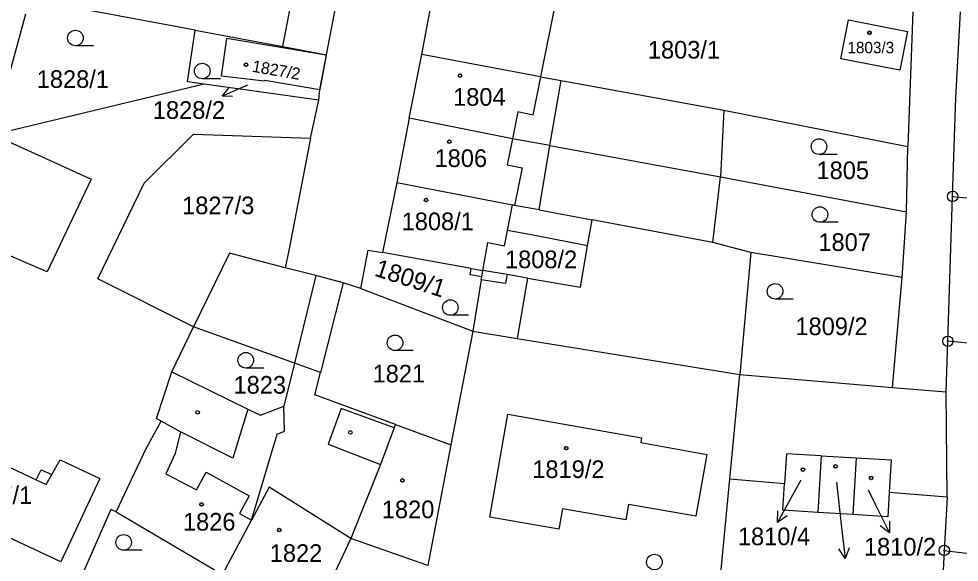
# Model space of a CAD drawing. Extents: x -593183 to -588034, y -1130415 to -1124994.
# Drawn here: x -590407.9 to -590317.4, y -1129215.7 to -1129163.3 of the extents above; entities that cross this region are included whole.
import ezdxf

# ---------------------------------------------------------------- set-up
doc = ezdxf.new("R2010")
doc.units = 0
for name, color, linetype in [('Vrstva 1', 7, 'Continuous'), ('Vrstva 16', 7, 'Continuous'), ('Vrstva 18', 7, 'Continuous'), ('Vrstva 19', 7, 'Continuous'), ('Vrstva 24', 7, 'Continuous'), ('Vrstva 25', 7, 'Continuous'), ('Vrstva 4', 7, 'Continuous')]:
    doc.layers.add(name, color=color, linetype=linetype)

msp = doc.modelspace()

# ---------------------------------------------------------------- linework, layer by layer
at = {"layer": 'Vrstva 1'}
for p, q in [((-590369.15, -1129166.78), (-590367.73, -1129159.34)), ((-590390.98, -1129164.42), (-590406.84, -1129161.45)), ((-590378.33, -1129166.8), (-590377.25, -1129161.25)), ((-590382.52, -1129166), (-590381.79, -1129162.16)), ((-590356.22, -1129161.56), (-590357.7, -1129168.92)), ((-590407.29, -1129162.87), (-590410.48, -1129174.52)), ((-590321.86, -1129162.66), (-590322.32, -1129175.65)), ((-590317.71, -1129170.96), (-590317.25, -1129162.67)), ((-590328.78, -1129167.18), (-590328.05, -1129163.42)), ((-590328.05, -1129163.42), (-590322.37, -1129164.54)), ((-590391.69, -1129169.4), (-590390.98, -1129164.42)), ((-590390.98, -1129164.42), (-590388.21, -1129164.94)), ((-590388.21, -1129164.94), (-590383.54, -1129165.82)), ((-590322.37, -1129164.54), (-590323.1, -1129168.29)), ((-590388.42, -1129168.86), (-590387.92, -1129165.22)), ((-590378.35, -1129166.84), (-590387.92, -1129165.22)), ((-590383.54, -1129165.82), (-590382.52, -1129166)), ((-590382.52, -1129166), (-590378.33, -1129166.8)), ((-590378.96, -1129170.14), (-590378.33, -1129166.8)), ((-590378.35, -1129166.84), (-590378.96, -1129170.14)), ((-590370.37, -1129172.89), (-590369.15, -1129166.78)), ((-590323.1, -1129168.29), (-590328.78, -1129167.18)), ((-590390.09, -1129169.62), (-590391.69, -1129169.4)), ((-590384.3, -1129169.35), (-590388.42, -1129168.86)), ((-590384.26, -1129169.23), (-590384.3, -1129169.35)), ((-590384.26, -1129169.23), (-590378.96, -1129170.14)), ((-590357.7, -1129168.92), (-590355.73, -1129169.28)), ((-590356.8, -1129175.55), (-590355.73, -1129169.28)), ((-590355.73, -1129169.28), (-590340.05, -1129172.13)), ((-590390.09, -1129169.62), (-590410.48, -1129174.52)), ((-590379.04, -1129171.16), (-590390.09, -1129169.62)), ((-590379.04, -1129171.16), (-590378.96, -1129170.14)), ((-590379.85, -1129174.84), (-590379.04, -1129171.16)), ((-590318.02, -1129180.44), (-590317.71, -1129170.96)), ((-590340.05, -1129172.13), (-590322.32, -1129175.65)), ((-590370.37, -1129172.89), (-590371.55, -1129179.1)), ((-590360.41, -1129174.88), (-590370.37, -1129172.89)), ((-590395.88, -1129179.17), (-590391.11, -1129174.46)), ((-590391.11, -1129174.46), (-590379.85, -1129174.84)), ((-590379.85, -1129174.84), (-590381.96, -1129185.64)), ((-590356.8, -1129175.55), (-590360.41, -1129174.88)), ((-590357.85, -1129181.75), (-590356.8, -1129175.55)), ((-590356.8, -1129175.55), (-590340.36, -1129178.57)), ((-590322.47, -1129181.93), (-590322.32, -1129175.65)), ((-590340.36, -1129178.57), (-590322.47, -1129181.93)), ((-590400.33, -1129188.4), (-590395.88, -1129179.17)), ((-590371.55, -1129179.1), (-590372.91, -1129185.84)), ((-590371.55, -1129179.1), (-590360.41, -1129181.27)), ((-590318.48, -1129194.4), (-590318.02, -1129180.44)), ((-590318.02, -1129180.44), (-590301.13, -1129182.05)), ((-590360.89, -1129183.72), (-590360.41, -1129181.27)), ((-590360.21, -1129181.31), (-590360.41, -1129181.27)), ((-590357.85, -1129181.75), (-590360.21, -1129181.31)), ((-590357.85, -1129181.75), (-590352.74, -1129182.71)), ((-590322.88, -1129188.25), (-590322.47, -1129181.93)), ((-590353.17, -1129185.2), (-590352.74, -1129182.71)), ((-590341.12, -1129184.9), (-590352.74, -1129182.71)), ((-590361.17, -1129185.19), (-590360.89, -1129183.72)), ((-590363.26, -1129187.58), (-590362.78, -1129184.9)), ((-590362.78, -1129184.9), (-590361.17, -1129185.19)), ((-590337.45, -1129185.84), (-590341.12, -1129184.9)), ((-590387.66, -1129185.9), (-590391.14, -1129193.02)), ((-590382.29, -1129187.32), (-590387.66, -1129185.9)), ((-590381.96, -1129185.64), (-590382.29, -1129187.32)), ((-590375.01, -1129189.31), (-590374.3, -1129185.62)), ((-590374.3, -1129185.62), (-590372.91, -1129185.84)), ((-590364.38, -1129187.38), (-590372.91, -1129185.84)), ((-590353.85, -1129189.19), (-590353.17, -1129185.2)), ((-590322.88, -1129188.25), (-590337.45, -1129185.84)), ((-590379.34, -1129188.07), (-590382.29, -1129187.32)), ((-590364.49, -1129188), (-590364.38, -1129187.38)), ((-590363.37, -1129188.2), (-590363.26, -1129187.58)), ((-590391.14, -1129193.02), (-590400.33, -1129188.4)), ((-590376.71, -1129188.78), (-590379.34, -1129188.07)), ((-590363.37, -1129188.2), (-590364.49, -1129188)), ((-590363.42, -1129188.47), (-590363.37, -1129188.2)), ((-590361.07, -1129188.84), (-590363.42, -1129188.47)), ((-590360.93, -1129187.98), (-590361.07, -1129188.84)), ((-590358.97, -1129188.31), (-590360.93, -1129187.98)), ((-590358.97, -1129188.31), (-590359.96, -1129194.13)), ((-590358.97, -1129188.31), (-590353.85, -1129189.19)), ((-590323.8, -1129198.84), (-590322.88, -1129188.25)), ((-590375.01, -1129189.31), (-590376.71, -1129188.78)), ((-590375.01, -1129189.31), (-590364.22, -1129193.44)), ((-590393.22, -1129197.36), (-590391.14, -1129193.02)), ((-590381.41, -1129196.5), (-590391.14, -1129193.02)), ((-590364.22, -1129193.44), (-590366.33, -1129204.39)), ((-590364.22, -1129193.44), (-590359.96, -1129194.13)), ((-590359.96, -1129194.13), (-590338.51, -1129197.6)), ((-590318.64, -1129199.27), (-590318.48, -1129194.4)), ((-590302.44, -1129195.96), (-590318.48, -1129194.4)), ((-590381.41, -1129196.5), (-590382.44, -1129200.67)), ((-590378.9, -1129197.42), (-590381.41, -1129196.5)), ((-590394.68, -1129201.84), (-590393.22, -1129197.36)), ((-590393.22, -1129197.36), (-590385.9, -1129200.93)), ((-590379.43, -1129199.55), (-590378.9, -1129197.42)), ((-590339.47, -1129207.66), (-590338.51, -1129197.6)), ((-590338.51, -1129197.6), (-590323.8, -1129198.84)), ((-590318.55, -1129209.43), (-590318.64, -1129199.27)), ((-590371.67, -1129202.42), (-590379.43, -1129199.55)), ((-590385.9, -1129200.93), (-590384.66, -1129201.52)), ((-590384.66, -1129201.52), (-590382.44, -1129200.67)), ((-590382.36, -1129203.07), (-590382.44, -1129200.67)), ((-590395.66, -1129204.68), (-590394.24, -1129202.11)), ((-590394.24, -1129202.11), (-590394.68, -1129201.84)), ((-590362.6, -1129211.36), (-590360.86, -1129201.43)), ((-590360.86, -1129201.43), (-590347.98, -1129203.69)), ((-590383.06, -1129203.35), (-590382.36, -1129203.07)), ((-590371.79, -1129202.73), (-590373.11, -1129206.26)), ((-590371.67, -1129202.42), (-590371.79, -1129202.73)), ((-590371.67, -1129202.42), (-590366.33, -1129204.39)), ((-590385.53, -1129211.63), (-590383.06, -1129203.35)), ((-590347.98, -1129203.69), (-590348.06, -1129204.16)), ((-590398.57, -1129210.83), (-590395.66, -1129204.68)), ((-590366.33, -1129204.39), (-590368.57, -1129216)), ((-590348.06, -1129204.16), (-590341.68, -1129205.32)), ((-590341.68, -1129205.32), (-590342.76, -1129211.26)), ((-590334.02, -1129205.24), (-590334.2, -1129208.11)), ((-590330.68, -1129205.43), (-590334.02, -1129205.24)), ((-590330.68, -1129205.43), (-590331, -1129210.89)), ((-590330.68, -1129205.43), (-590327.31, -1129205.63)), ((-590327.31, -1129205.63), (-590327.63, -1129211.08)), ((-590327.31, -1129205.63), (-590323.94, -1129205.83)), ((-590323.94, -1129205.83), (-590324.12, -1129208.96)), ((-590373.11, -1129206.26), (-590375.96, -1129213.4)), ((-590341.15, -1129225.34), (-590339.47, -1129207.66)), ((-590339.47, -1129207.66), (-590334.2, -1129208.11)), ((-590334.37, -1129210.69), (-590334.2, -1129208.11)), ((-590324.12, -1129208.96), (-590324.26, -1129211.31)), ((-590318.55, -1129209.43), (-590324.12, -1129208.96)), ((-590318.55, -1129209.43), (-590318.83, -1129214.55)), ((-590349.23, -1129210.13), (-590349.49, -1129211.61)), ((-590342.76, -1129211.26), (-590349.23, -1129210.13)), ((-590399.1, -1129210.62), (-590403.83, -1129221.39)), ((-590398.57, -1129210.83), (-590399.1, -1129210.62)), ((-590398.57, -1129210.83), (-590388.33, -1129216.89)), ((-590355.6, -1129210.55), (-590355.94, -1129212.52)), ((-590349.49, -1129211.61), (-590355.6, -1129210.55)), ((-590331, -1129210.89), (-590334.37, -1129210.69)), ((-590327.63, -1129211.08), (-590331, -1129210.89)), ((-590324.26, -1129211.31), (-590327.63, -1129211.08)), ((-590388.33, -1129216.89), (-590385.53, -1129211.63)), ((-590355.94, -1129212.52), (-590362.6, -1129211.36)), ((-590375.96, -1129213.4), (-590378.66, -1129219.07)), ((-590318.83, -1129214.55), (-590319.63, -1129229.39)), ((-590318.83, -1129214.55), (-590304.37, -1129216.34))]:
    msp.add_line(p, q, dxfattribs=at)
at = {"layer": 'Vrstva 16'}
for p, q in [((-590332.64, -1129207.77), (-590333.44, -1129209.22)), ((-590329.19, -1129207.99), (-590328.71, -1129212.36)), ((-590326.17, -1129208.72), (-590325.44, -1129210.17))]:
    msp.add_line(p, q, dxfattribs=at)
at = {"layer": 'Vrstva 24'}
for centre, radius in [((-590318.02, -1129180.44), 0.5), ((-590318.02, -1129180.44), 0.0327), ((-590318.48, -1129194.4), 0.5), ((-590318.48, -1129194.4), 0.0327), ((-590318.83, -1129214.55), 0.5), ((-590318.83, -1129214.55), 0.0327)]:
    msp.add_circle(centre, radius, dxfattribs=at)
at = {"layer": 'Vrstva 25'}
for p, q in [((-590400.75, -1129165.93), (-590402.5, -1129165.93)), ((-590388.53, -1129169.11), (-590390.28, -1129169.11)), ((-590385.93, -1129169.74), (-590388.36, -1129170.773)), ((-590329.14, -1129176.39), (-590330.89, -1129176.39)), ((-590329.05, -1129182.94), (-590330.8, -1129182.94)), ((-590333.37, -1129190.34), (-590335.12, -1129190.34)), ((-590364.64, -1129191.9), (-590366.39, -1129191.9)), ((-590369.96, -1129195.3), (-590371.71, -1129195.3)), ((-590384.34, -1129196.98), (-590386.09, -1129196.98)), ((-590333.44, -1129209.22), (-590334.887, -1129211.848)), ((-590325.44, -1129210.17), (-590324.094, -1129212.851)), ((-590328.71, -1129212.36), (-590328.384, -1129215.342)), ((-590396.1, -1129214.53), (-590397.85, -1129214.53))]:
    msp.add_line(p, q, dxfattribs=at)
for points in [[(-590387.378, -1129170.833), (-590388.36, -1129170.773), (-590387.722, -1129170.023)], [(-590333.967, -1129211.213), (-590334.887, -1129211.848), (-590334.843, -1129210.731)], [(-590324.096, -1129211.733), (-590324.094, -1129212.851), (-590324.99, -1129212.182)], [(-590327.996, -1129214.294), (-590328.384, -1129215.342), (-590328.99, -1129214.402)]]:
    msp.add_lwpolyline(points, dxfattribs=at)
for centre, radius in [((-590402.5, -1129165.18), 0.75), ((-590326.03, -1129164.68), 0.175), ((-590326.03, -1129164.68), 0.15), ((-590390.28, -1129168.36), 0.75), ((-590386.07, -1129167.75), 0.175), ((-590386.07, -1129167.75), 0.15), ((-590365.46, -1129168.8), 0.175), ((-590365.46, -1129168.8), 0.15), ((-590366.49, -1129175.17), 0.175), ((-590366.49, -1129175.17), 0.15), ((-590330.89, -1129175.64), 0.75), ((-590368.74, -1129180.79), 0.175), ((-590368.74, -1129180.79), 0.15), ((-590330.8, -1129182.19), 0.75), ((-590335.12, -1129189.59), 0.75), ((-590366.39, -1129191.15), 0.75), ((-590371.71, -1129194.55), 0.75), ((-590386.09, -1129196.23), 0.75), ((-590390.73, -1129201.25), 0.175), ((-590376.02, -1129203.19), 0.175), ((-590355.23, -1129204.7), 0.175), ((-590355.23, -1129204.7), 0.15), ((-590332.44, -1129206.77), 0.175), ((-590332.44, -1129206.77), 0.15), ((-590329.29, -1129206.46), 0.175), ((-590329.29, -1129206.46), 0.15), ((-590371.01, -1129207.81), 0.175), ((-590325.87, -1129207.57), 0.175), ((-590325.87, -1129207.57), 0.15), ((-590371.01, -1129207.81), 0.15), ((-590390.35, -1129210.12), 0.175), ((-590390.35, -1129210.12), 0.15), ((-590397.85, -1129213.78), 0.75), ((-590382.87, -1129212.59), 0.175), ((-590382.87, -1129212.59), 0.15), ((-590346.74, -1129215.68), 0.75)]:
    msp.add_circle(centre, radius, dxfattribs=at)
at = {"layer": 'Vrstva 4'}
for p, q in [((-590357.7, -1129168.92), (-590369.15, -1129166.78)), ((-590357.7, -1129168.92), (-590358.44, -1129172.6)), ((-590359.9, -1129172.31), (-590360.41, -1129174.88)), ((-590358.44, -1129172.6), (-590359.9, -1129172.31)), ((-590340.05, -1129172.13), (-590340.36, -1129178.57)), ((-590410.16, -1129174.62), (-590400.99, -1129178.78)), ((-590360.41, -1129174.88), (-590360.91, -1129177.41)), ((-590360.91, -1129177.41), (-590359.49, -1129177.69)), ((-590359.49, -1129177.69), (-590360.21, -1129181.31)), ((-590341.12, -1129184.9), (-590340.36, -1129178.57)), ((-590400.99, -1129178.78), (-590405.21, -1129187.72)), ((-590405.21, -1129187.72), (-590414.45, -1129183.77)), ((-590358.27, -1129184.22), (-590360.89, -1129183.72)), ((-590353.17, -1129185.2), (-590358.27, -1129184.22)), ((-590337.45, -1129185.84), (-590338.51, -1129197.6)), ((-590364.38, -1129187.38), (-590363.26, -1129187.58)), ((-590360.93, -1129187.98), (-590363.26, -1129187.58)), ((-590379.34, -1129188.07), (-590381.41, -1129196.5)), ((-590363.42, -1129188.47), (-590364.22, -1129193.44)), ((-590376.71, -1129188.78), (-590378.9, -1129197.42)), ((-590323.8, -1129198.84), (-590318.64, -1129199.27)), ((-590385.9, -1129200.93), (-590387.33, -1129205.67)), ((-590376.89, -1129200.89), (-590378.16, -1129204.33)), ((-590371.79, -1129202.73), (-590376.89, -1129200.89)), ((-590419.01, -1129201.76), (-590406.26, -1129207.74)), ((-590392.39, -1129203.14), (-590394.24, -1129202.11)), ((-590392.39, -1129203.14), (-590392.9, -1129205.23)), ((-590387.33, -1129205.67), (-590392.39, -1129203.14)), ((-590378.16, -1129204.33), (-590373.11, -1129206.26)), ((-590404.78, -1129207.25), (-590403.98, -1129205.81)), ((-590403.98, -1129205.81), (-590400.16, -1129207.62)), ((-590392.9, -1129205.23), (-590393.8, -1129207.17)), ((-590403.9, -1129215.64), (-590421.67, -1129207.34)), ((-590406.26, -1129207.74), (-590405.81, -1129206.78)), ((-590405.81, -1129206.78), (-590404.78, -1129207.25)), ((-590405.3, -1129208.19), (-590404.78, -1129207.25)), ((-590400.16, -1129207.62), (-590403.9, -1129215.64)), ((-590393.8, -1129207.17), (-590390.82, -1129208.72)), ((-590390.82, -1129208.72), (-590389.9, -1129207.03)), ((-590389.9, -1129207.03), (-590385.76, -1129209.3)), ((-590406.26, -1129207.74), (-590405.3, -1129208.19)), ((-590383.84, -1129208.47), (-590385.53, -1129211.63)), ((-590375.96, -1129213.4), (-590383.84, -1129208.47)), ((-590385.76, -1129209.3), (-590386.69, -1129211)), ((-590386.69, -1129211), (-590385.53, -1129211.63)), ((-590368.57, -1129216), (-590375.96, -1129213.4))]:
    msp.add_line(p, q, dxfattribs=at)

# ---------------------------------------------------------------- texts
at = {"layer": 'Vrstva 16'}
for s, p in [('1828/2', (-590395.04, -1129172.97)), ('1810/4', (-590338.7, -1129214.05)), ('1810/2', (-590326.56, -1129215.05))]:
    msp.add_text(s, height=1.7, dxfattribs=at).set_placement(p)
at = {"layer": 'Vrstva 18'}
for s, height, p in [('1803/1', 1.7, (-590347.37, -1129167.16)), ('1828/1', 1.7, (-590406.22, -1129169.99)), ('1828/2', 0.01, (-590385.93, -1129169.74)), ('1805', 1.7, (-590331.13, -1129178.78)), ('1827/3', 1.7, (-590392.22, -1129182.16)), ('1807', 1.7, (-590330.95, -1129185.7)), ('1808/2', 1.7, (-590361.13, -1129187.36)), ('1809/2', 1.7, (-590333.16, -1129193.81)), ('1821', 1.7, (-590373.88, -1129198.37)), ('1823', 1.7, (-590387.27, -1129199.45))]:
    msp.add_text(s, height=height, dxfattribs=at).set_placement(p)
msp.add_text('1809/1', height=1.7, rotation=342, dxfattribs=at).set_placement((-590373.8, -1129188.06))
at = {"layer": 'Vrstva 19'}
for s, height, p in [('1803/3', 1.1, (-590328.15, -1129166.65)), ('1804', 1.7, (-590366.13, -1129171.71)), ('1806', 1.7, (-590367.91, -1129177.61)), ('1808/1', 1.7, (-590371.08, -1129183.7)), ('1819/2', 1.7, (-590358.5, -1129207.58)), ('1827/1', 1.7, (-590413.61, -1129210.08)), ('1810/4', 0.01, (-590332.64, -1129207.77)), ('1810/3', 0.01, (-590329.19, -1129207.99)), ('1810/2', 0.01, (-590326.17, -1129208.72)), ('1820', 1.7, (-590372.99, -1129211.45)), ('1826', 1.7, (-590392.14, -1129212.64)), ('1822', 1.7, (-590383.78, -1129215.66))]:
    msp.add_text(s, height=height, dxfattribs=at).set_placement(p)
msp.add_text('1827/2', height=1.14, rotation=350.20773, dxfattribs=at).set_placement((-590385.539, -1129168.427))

doc.saveas('drawing.dxf')
